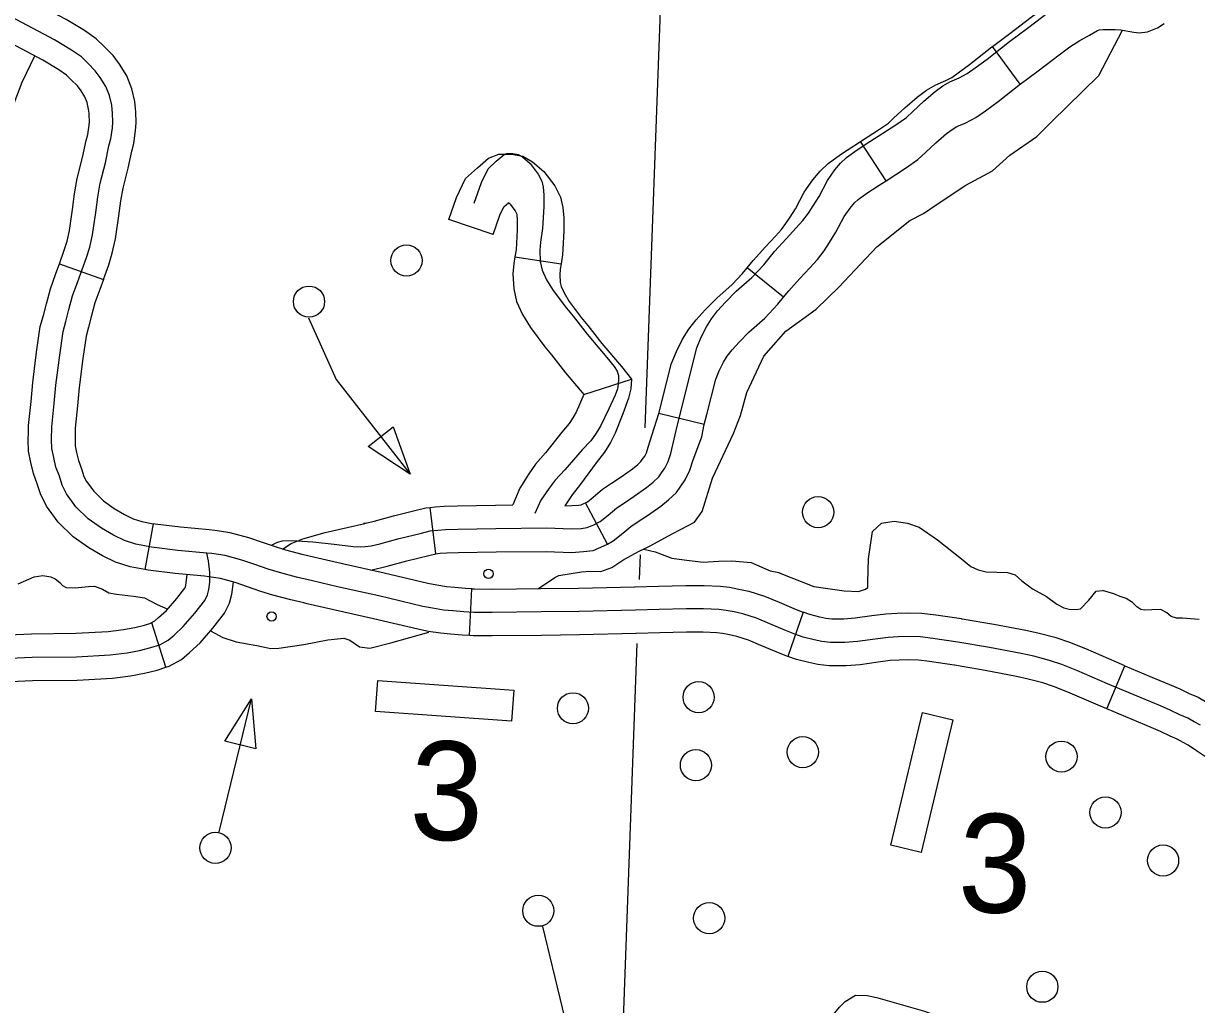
# Model space of a CAD drawing. Extents: x 653372 to 905732, y 627442 to 787275.
# Drawn here: x 719343 to 723106, y 752725 to 755873 of the extents above; entities that cross this region are included whole.
import ezdxf

# ---------------------------------------------------------------- set-up
doc = ezdxf.new("R2010")
doc.units = 0
for name, color, linetype in [('31', 7, 'Continuous'), ('32', 7, 'Continuous'), ('35', 7, 'Continuous'), ('4', 7, 'Continuous'), ('56', 7, 'Continuous')]:
    doc.layers.add(name, color=color, linetype=linetype)

msp = doc.modelspace()

# ---------------------------------------------------------------- linework, layer by layer
at = {"layer": '31'}
for p, q in [((719458.4, 755102.1), (719599.7, 755051.5)), ((719508.7, 754559), (719508.7, 754559)), ((719759.2, 754267.9), (719732.1, 754120.4)), ((720773.8, 753908.9), (720781.3, 754058.7)), ((721843.9, 753983.7), (721795.2, 753841.8)), ((721795.2, 753841.8), (721795.2, 753841.8)), ((722818, 753673.6), (722875.9, 753812))]:
    msp.add_line(p, q, dxfattribs=at)
for points in [[(719702.6, 755600.9), (719700.3, 755623.4), (719690.5, 755664.1), (719675, 755704.8), (719651.2, 755742.5), (719630.3, 755770.3), (719602.2, 755799.4), (719576.4, 755824), (719538.4, 755850.5), (719479.5, 755886.4), (719339.1, 755960.5), (719283, 755990.6)], [(719930.9, 754173.6), (719838.2, 754182.3), (719754, 754192.6), (719703.6, 754201.9), (719666.7, 754214.3), (719631.9, 754230.8), (719593.2, 754253.8), (719551.1, 754283.2), (719511.5, 754322.5), (719481, 754363.5), (719467.1, 754391.4), (719458.1, 754419.9), (719447, 754449.8), (719440.2, 754480.3), (719434, 754509.3), (719433.4, 754537.5), (719434, 754578.9), (719441.8, 754653.3), (719447.1, 754713), (719459.2, 754808.7), (719470.6, 754885.1), (719479.3, 754917.3), (719488.9, 754955), (719500.8, 754999), (719517.7, 755045), (719545.3, 755122.4), (719555.5, 755155.6), (719564.4, 755195.5), (719575, 755266.3), (719581.4, 755315.4), (719589.1, 755360.3), (719605.9, 755426.5), (719617.4, 755480.4), (719623, 755502.8), (719628.3, 755538.5), (719629.5, 755556.8), (719628.9, 755584.6), (719626.2, 755610.7), (719618.7, 755641.9), (719607.6, 755671.1), (719589.4, 755699.9), (719573.2, 755721.5), (719549.3, 755746.1), (719528.8, 755765.8), (719497.4, 755787.7), (719442.4, 755821.2), (719303.9, 755894.3)], [(719553.4, 755585.3), (719552.1, 755598), (719546.9, 755619.8), (719540.2, 755637.5), (719527.7, 755657.2), (719516.1, 755672.7), (719496.4, 755692.9), (719481.1, 755707.6), (719456.4, 755724.8), (719405.3, 755756), (719268.7, 755828.1), (719212.1, 755858.4)], [(719458.4, 755102.1), (719474.1, 755146), (719482.9, 755174.8), (719490.7, 755209.3), (719500.7, 755276.7), (719507.2, 755326.6), (719515.7, 755375.8), (719532.8, 755443.5), (719544.3, 755497.3), (719549.3, 755517.4), (719553.6, 755546.6), (719554.5, 755558.6), (719554, 755579.9), (719553.4, 755585.3)], [(719599.7, 755051.5), (719616.6, 755098.8), (719628.1, 755136.4), (719638.2, 755181.7), (719649.3, 755255.9), (719655.6, 755304.2), (719662.5, 755344.7), (719678.9, 755409.5), (719690.4, 755463.5), (719696.6, 755488.1), (719702.9, 755530.4), (719704.6, 755555), (719703.9, 755589.3), (719702.6, 755600.9)], [(719358.7, 754560.9), (719359, 754583.3), (719367.2, 754660.6), (719372.6, 754721.1), (719384.9, 754818.9), (719397.1, 754900.5), (719406.8, 754936.3), (719416.4, 754974), (719429.3, 755021.8), (719447.2, 755070.6), (719458.4, 755102.1)], [(719599.7, 755051.5), (719588.2, 755019.5), (719572.3, 754976.3), (719561.5, 754936), (719551.9, 754898.2), (719544.2, 754869.7), (719533.5, 754798.5), (719521.7, 754705), (719516.5, 754646.1), (719508.9, 754574.5), (719508.7, 754559)], [(719732.1, 754120.4), (719684.8, 754129.1), (719638.5, 754144.6), (719596.6, 754164.6), (719552.5, 754190.7), (719502.9, 754225.4), (719454.6, 754273.2), (719416.9, 754324.1), (719397.3, 754363.2), (719387.1, 754395.5), (719374.9, 754428.5), (719366.9, 754464.3), (719359.1, 754500.7), (719358.4, 754537.3), (719358.7, 754560.9)], [(719508.7, 754559), (719508.4, 754537.8), (719508.8, 754518), (719513.4, 754496.3), (719519.1, 754471.1), (719529, 754444.2), (719536.8, 754419.7), (719545.2, 754402.9), (719568.3, 754371.8), (719599.3, 754341), (719633.9, 754316.9), (719667.3, 754297), (719694.8, 754283.9), (719722.4, 754274.7), (719759.2, 754267.9)], [(720278, 754159.3), (720237.1, 754169.2), (720184.5, 754183), (720151.6, 754193.1), (720109.8, 754207.6), (720065.6, 754222.5), (720005.8, 754238.9), (719957.3, 754246.2), (719938.6, 754248.2), (719846.3, 754256.9), (719765.4, 754266.8), (719759.2, 754267.9)], [(721382.2, 753992.4), (721306.7, 753990.2), (721125.5, 753986), (721003.8, 753984.5), (720846.4, 753982.9), (720787.5, 753983.3), (720755.6, 753984.9), (720720, 753987.9), (720690.6, 753990.7), (720655.6, 753996.3), (720624.4, 754002.3), (720483.1, 754036), (720350.3, 754065.6), (720270.2, 754084), (720218.8, 754096.4), (720163.9, 754110.9), (720128.3, 754121.8), (720085.5, 754136.7), (720043.7, 754150.7), (719990.3, 754165.4), (719947.6, 754171.8), (719930.9, 754173.6)], [(720781.3, 754058.7), (720760.6, 754059.8), (720726.7, 754062.6), (720700.1, 754065.2), (720668.6, 754070.1), (720640.3, 754075.6), (720500, 754109.1), (720366.9, 754138.7), (720287.4, 754157), (720278, 754159.3)], [(720242.8, 754013.5), (720200.4, 754023.7), (720143.4, 754038.7), (720105, 754050.5), (720061.2, 754065.7), (720021.8, 754079), (719974.7, 754091.9), (719937.9, 754097.4), (719923.3, 754099), (719830.2, 754107.8), (719742.7, 754118.5), (719732.1, 754120.4)], [(720781.3, 754058.7), (720789.7, 754058.3), (720846.3, 754057.9), (721003, 754059.5), (721124.1, 754061), (721303.7, 754065.1)], [(721303.8, 754065.1), (721304.7, 754065.1), (721380.3, 754067.3), (721467.7, 754069.2), (721526.5, 754069.5), (721579.4, 754067.2), (721608.5, 754063.9), (721638.1, 754057.9), (721670.3, 754051.1), (721720.6, 754034.8), (721766.8, 754015.6), (721813.9, 753995.3), (721843.5, 753983.8), (721843.9, 753983.7)], [(720773.8, 753908.9), (720750.6, 753910.1), (720713.3, 753913.2), (720681.2, 753916.3), (720642.6, 753922.4), (720608.6, 753929), (720466.3, 753962.9), (720333.8, 753992.4), (720253, 754011), (720242.8, 754013.5)], [(723118.6, 753621.5), (723099.1, 753631.7), (723078, 753643.8), (723052.3, 753654.8), (723021.8, 753669.2), (722990.2, 753682.9), (722928.9, 753708.5), (722820.2, 753754), (722722, 753796.6), (722673.9, 753816), (722634.6, 753829.3), (722583.8, 753842.4), (722543.8, 753851.2), (722442.1, 753870.7), (722340.8, 753888.1), (722259.9, 753899.4), (722219.7, 753904.5), (722178.8, 753905.7), (722149.3, 753904.7), (722116.7, 753903.1), (722074.9, 753897.3), (722019, 753890), (721978.3, 753886.8), (721953.3, 753886.2), (721932.2, 753886.2), (721904.1, 753889.6), (721880, 753894.9), (721844.4, 753904.2), (721817.8, 753913.4), (721785.6, 753925.8), (721737.6, 753946.5), (721694.6, 753964.4), (721650.9, 753978.5), (721622.9, 753984.5), (721596.8, 753989.8), (721573.6, 753992.4), (721525, 753994.5), (721468.7, 753994.2), (721382.2, 753992.4)], [(722354.6, 753961.8), (722352.3, 753962.2), (722269.8, 753973.8), (722225.5, 753979.4), (722178.6, 753980.8), (722146.2, 753979.6), (722109.7, 753977.9), (722064.9, 753971.7), (722011.2, 753964.6), (721974.5, 753961.7), (721952.5, 753961.2), (721936.7, 753961.2), (721916.6, 753963.7), (721897.5, 753967.8), (721866.2, 753976.1), (721843.9, 753983.7)], [(722875.9, 753812), (722849.6, 753823), (722750.9, 753865.8), (722700, 753886.3), (722656.1, 753901.2), (722601.3, 753915.3), (722559, 753924.7), (722455.5, 753944.5), (722354.6, 753961.8)], [(721307.2, 753915.1), (721126.8, 753911), (721004.7, 753909.5), (720846.5, 753907.8), (720785.4, 753908.4), (720773.8, 753908.9)], [(721795.2, 753841.8), (721792.1, 753842.9), (721757.2, 753856.4), (721708.3, 753877.4), (721668.6, 753894), (721631.5, 753906), (721607.7, 753911.1), (721585.2, 753915.6), (721567.7, 753917.6), (721523.5, 753919.5), (721469.6, 753919.3), (721384.1, 753917.4), (721308.6, 753915.2), (721307.1, 753915.1)], [(722329.3, 753813.9), (722329.2, 753813.9), (722250, 753825.1), (722213.9, 753829.6), (722179, 753830.7), (722152.5, 753829.7), (722123.6, 753828.4), (722084.9, 753823), (722026.8, 753815.4), (721982.1, 753811.8), (721954.1, 753811.2), (721927.7, 753811.2), (721891.7, 753815.6), (721862.5, 753821.9), (721822.7, 753832.4), (721795.2, 753841.8)], [(722818, 753673.6), (722790.8, 753685), (722693, 753727.4), (722647.8, 753745.6), (722613.2, 753757.4), (722566.4, 753769.4), (722528.6, 753777.8), (722428.7, 753796.9), (722329.3, 753813.9)], [(722875.9, 753812), (722957.8, 753777.7), (723019.6, 753751.9), (723052.7, 753737.5), (723083.1, 753723.3), (723111.7, 753711), (723135.2, 753697.4), (723157.7, 753685.7), (723190.4, 753662.7), (723227.7, 753637.9), (723271.5, 753605.1), (723294.3, 753590.6), (723346.9, 753562.3)], [(723275.9, 753430.2), (723218.6, 753461), (723186.2, 753481.5), (723141.2, 753515.3), (723105.7, 753538.8), (723079.5, 753557.3), (723063, 753565.9), (723044.3, 753576.7), (723021.6, 753586.4), (722990.9, 753600.8), (722960.8, 753613.9), (722900, 753639.2), (722818, 753673.6)]]:
    msp.add_lwpolyline(points, dxfattribs=at)
at = {"layer": '32'}
for p, q in [((722540.4, 755678.8), (722451.3, 755799.4)), ((722110.3, 755368.7), (722028.4, 755494.5)), ((720849.5, 755196), (720707.6, 755244.5)), ((720919.6, 755124.8), (721067.7, 755101.5)), ((721781.3, 754994.6), (721664.9, 755089.2)), ((721140.9, 754682.8), (721294.1, 754731.6)), ((721527, 754586.2), (721381.3, 754621.8)), ((720665.4, 754171.1), (720648.2, 754320.1)), ((721216.9, 754202.7), (721145.9, 754334.9)), ((719800, 753807), (719754.5, 753949.9))]:
    msp.add_line(p, q, dxfattribs=at)
for points in [[(722451.3, 755799.4), (722507.6, 755841), (722575.4, 755893.1), (722615.7, 755922.3), (722654.8, 755947.3), (722687.3, 755965.2), (722725.8, 755988.8), (722762.7, 756000.2), (722798.8, 756004.5), (722850.1, 756003.7), (722881.1, 756002), (722911.5, 755996.3), (722915.1, 755995.8), (722919.7, 755998.9)], [(721843.5, 755241.2), (721861.1, 755264.3), (721876.9, 755288), (721895.4, 755317.7), (721922.9, 755369.5), (721946.3, 755403.3), (721964.5, 755425.2), (721983.2, 755443.4), (722017.2, 755467.8), (722058.6, 755494.4), (722141.3, 755548.2), (722175.9, 755571.9), (722196.4, 755591.3), (722231.3, 755623.5), (722267.9, 755655.1), (722292, 755673.2), (722314.8, 755686.4), (722344.9, 755699.4), (722370.7, 755712.6), (722396.6, 755730.5), (722435, 755759), (722506.3, 755815.6), (722563.6, 755858), (722631.1, 755909.8)], [(722540.4, 755678.8), (722597.9, 755721.2), (722665.1, 755772.8), (722700.2, 755798.3), (722731.5, 755818.3), (722762.6, 755835.5), (722788.1, 755851.1), (722794, 755852.9), (722806.5, 755854.4), (722844.7, 755853.8), (722863.2, 755852.8), (722886.9, 755848.3), (722905.2, 755845.7), (722922.1, 755843.7), (722949.2, 755846.8), (722980.9, 755859.6), (723002, 755873.5)], [(722028.4, 755494.5), (722088.7, 755533.7), (722117.8, 755553.6), (722134.4, 755569.3), (722170.4, 755602.6), (722210, 755636.8), (722239.7, 755659), (722270.1, 755676.6), (722302, 755690.4), (722321.2, 755700.2), (722342, 755714.6), (722378.4, 755741.7), (722449.7, 755798.3), (722451.2, 755799.4)], [(722110.3, 755368.7), (722172.1, 755409), (722212.2, 755436.5), (722236.7, 755459.6), (722270.3, 755490.7), (722304, 755519.8), (722322.6, 755533.6), (722337.8, 755542.5), (722365.9, 755554.7), (722398.3, 755571.2), (722429.5, 755592.7), (722469.8, 755622.7), (722541, 755679.2), (722540.5, 755678.8)], [(721664.9, 755089.2), (721684.4, 755113.1), (721723.4, 755156), (721755.3, 755190.7), (721774.9, 755212.4), (721789.2, 755231), (721803, 755251.7), (721819.4, 755278.3), (721847.9, 755331.8), (721875.7, 755371.9), (721898.5, 755399.3), (721924.1, 755424.2), (721964.2, 755453), (722007, 755480.5), (722028.4, 755494.5)], [(720707.6, 755244.5), (720731.7, 755315.2), (720761.3, 755375.8), (720799.1, 755410.4), (720834.7, 755441), (720868.3, 755453.8), (720908.4, 755454.1), (720945.5, 755447), (720975.9, 755429.8), (721012.5, 755398.5), (721047.4, 755352.5), (721066, 755316.1), (721073.8, 755283.2), (721076.6, 755249.8), (721077, 755207.3), (721072.3, 755130.7), (721067.7, 755101.5)], [(720789.4, 755297.1), (720812.1, 755363.4), (720833.3, 755407), (720859.7, 755431.1), (720884.6, 755452.5), (720893.2, 755455.8), (720912.5, 755455.9), (720930.2, 755452.5), (720943.5, 755445), (720968.5, 755423.6), (720994.6, 755389.3), (721006, 755366.8), (721010.4, 755348.2), (721012.5, 755323.2), (721012.8, 755286.1), (721008.6, 755215.7), (721001.5, 755171), (720999.3, 755145.4), (721001.1, 755109), (721007.4, 755081.7), (721021.4, 755050.6), (721042.3, 755016.2), (721084.8, 754959.3), (721106.3, 754933.9)], [(721781.3, 754994.6), (721798.1, 755015.3), (721834.1, 755054.8), (721866.1, 755089.6), (721890.3, 755116.3), (721911.3, 755143.8), (721929.1, 755170.5), (721949.5, 755203.4), (721976.2, 755253.6), (721995.2, 755281), (722008.8, 755297.3), (722020.6, 755308.9), (722048.5, 755328.9), (722088.4, 755354.5), (722110.3, 755368.7)], [(720849.5, 755196), (720870.7, 755257.9), (720883.6, 755284.4), (720898.6, 755298.1), (720898.8, 755298.3), (720902.8, 755295), (720919.9, 755272.4), (720924.2, 755263.9), (720925.3, 755259.5), (720926.7, 755242.9), (720926.9, 755211.2), (720923.1, 755146.9), (720919.6, 755124.8)], [(720139.2, 754198.6), (720158.2, 754209), (720173.5, 754212.7), (720202.6, 754214.3), (720270.8, 754209.8), (720340.1, 754201.7), (720401, 754194.4), (720422.8, 754193.7), (720439.7, 754194.5), (720458.6, 754196.9), (720486, 754203.4), (720548.4, 754220.2), (720620.4, 754238), (720647.2, 754244.5), (720672.1, 754247.4), (720696.9, 754249.7), (720736.9, 754250.3), (720858, 754252.7), (721021.5, 754254.1), (721100.2, 754250.9), (721132.3, 754252.9), (721151.1, 754255.4), (721173.2, 754264.4), (721193.5, 754275.3), (721218.3, 754295.1), (721246.2, 754319.1), (721270.9, 754335.3), (721302.4, 754356.2), (721341.9, 754384), (721363, 754401.5), (721381.1, 754418), (721389.9, 754431), (721400.9, 754446.6), (721411.2, 754467.5), (721419.3, 754493.3), (721437.2, 754567.2), (721473.1, 754713.8), (721503.3, 754832.4), (721517.6, 754866.5), (721533.7, 754899.9), (721550.2, 754925.4), (721569.7, 754950.9), (721595.4, 754979.1), (721629.7, 755013.8), (721680.1, 755058.5), (721717.6, 755098.5), (721752.1, 755141), (721789.7, 755182.3), (721821.6, 755217), (721843.5, 755241.2)], [(720919.6, 755124.8), (720916.2, 755103.2), (720913.3, 755069.9), (720915.6, 755021.8), (720925.1, 754980.7), (720944.1, 754938.8), (720969.1, 754897.4), (721015.1, 754835.8), (721037, 754809.9), (721081.8, 754751.6), (721140.9, 754682.8)], [(721067.7, 755101.5), (721065.2, 755085.1), (721063.6, 755067.1), (721064.8, 755042.4), (721067.9, 755028.9), (721077.1, 755008.8), (721093.7, 754981.3), (721132.6, 754929.2), (721153.8, 754904.1), (721198.3, 754846.3), (721261.9, 754772.1), (721294.1, 754731.6)], [(721381.3, 754621.8), (721389.4, 754655.1), (721421.1, 754779.5), (721438.3, 754820.5), (721457.3, 754859.8), (721478, 754891.8), (721501.2, 754922.1), (721530.1, 754953.9), (721567.2, 754991.5), (721616.8, 755035.4), (721650.1, 755071), (721664.9, 755089.2)], [(721527, 754586.2), (721535, 754618.8), (721563.7, 754731.6), (721575.1, 754758.8), (721588.4, 754786.2), (721600.7, 754805.3), (721616.5, 754825.9), (721639, 754850.7), (721670.4, 754882.5), (721721.5, 754927.8), (721763.2, 754972.3), (721781.3, 754994.6)], [(721106.3, 754933.9), (721150.9, 754875.8), (721215, 754801.2), (721237.6, 754772.7), (721247.1, 754757.4), (721251.7, 754743.8), (721252.1, 754731.6), (721250.9, 754715.3), (721248.3, 754701.1), (721241.3, 754680.6), (721221.4, 754636.6), (721194.1, 754581.1), (721179.9, 754558), (721162.8, 754534.3), (721135.5, 754504.5), (721080.2, 754440.5), (721048.6, 754407.1), (721029.3, 754382), (721003.1, 754343.5), (720993.2, 754322.4), (720983.3, 754300.6)], [(721294.1, 754731.6), (721291.1, 754700.6), (721283.5, 754670.8), (721265.7, 754620.8), (721241.2, 754558.8), (721226.1, 754529), (721207.4, 754497.9), (721180.6, 754463.3), (721130.3, 754394.6), (721103, 754360.4), (721079.9, 754324.7)], [(721140.9, 754682.8), (721115.9, 754626.3), (721105.8, 754608.1), (721093.6, 754589.6), (721069.7, 754561.2), (721017.5, 754495.4), (720986, 754459), (720964.4, 754428.3), (720935.5, 754381.8), (720913.1, 754328.2)], [(721145.9, 754334.9), (721152, 754338.2), (721170.4, 754352.9), (721201, 754379.2), (721229.6, 754397.9), (721260.1, 754418.1), (721296.3, 754443.6), (721313.8, 754458.2), (721324, 754467.4), (721328.2, 754473.6), (721336.2, 754485), (721341.4, 754495.4), (721347, 754513.3), (721366.5, 754574.4), (721381.3, 754621.8)], [(721216.9, 754202.7), (721235, 754212.5), (721266.1, 754237.4), (721291.4, 754259.1), (721312.2, 754272.7), (721344.7, 754294.2), (721387.6, 754324.4), (721412.2, 754344.9), (721438.1, 754368.5), (721451.6, 754388.4), (721465.6, 754408.3), (721481.1, 754439.6), (721491.6, 754473.3), (721518.9, 754546.3), (721527, 754586.2)], [(720434.1, 754269.4), (720445.1, 754270.8), (720467.6, 754276.1), (720529.6, 754292.8), (720602.6, 754310.9), (720634, 754318.5), (720648.2, 754320.1)], [(720648.2, 754320.1), (720664.3, 754322), (720692.9, 754324.6), (720735.6, 754325.3), (720856.9, 754327.7), (720913.1, 754328.2)], [(721079.9, 754324.7), (721125, 754327.6), (721131.7, 754328.5), (721141.2, 754332.4), (721145.9, 754334.9)], [(720173.6, 754185.9), (720201.4, 754204.2), (720239, 754219.7), (720311, 754239.9), (720381, 754255.8), (720437.7, 754268.4), (720445.1, 754270.8)], [(720665.4, 754171.1), (720679.8, 754172.8), (720701, 754174.7), (720738.2, 754175.3), (720859.1, 754177.7), (721020.3, 754179.1), (721101, 754175.8), (721139.6, 754178.2), (721170.5, 754182.3), (721205.2, 754196.5), (721216.9, 754202.7)], [(719298.5, 753836.6), (719370.5, 753839.1), (719513.2, 753841), (719621.6, 753847), (719675.2, 753853.9), (719715.6, 753861.2), (719751.5, 753870.2), (719780.4, 753879.4), (719807.1, 753894.1), (719826.1, 753910.5), (719855.6, 753937.5), (719892.4, 753980.3), (719924.6, 754021.1), (719933.6, 754039.4), (719938, 754056.3), (719941, 754080.2), (719941.2, 754111.5), (719936.9, 754148.8), (719930.9, 754173.6)], [(720457.9, 754119.1), (720509.5, 754131.2), (720572.4, 754148.2), (720643.3, 754165.8), (720665.4, 754171.1), (720670.6, 754171.7)], [(719750.7, 753948.7), (719764.1, 753956), (719776.3, 753966.6), (719801.6, 753989.8), (719834.5, 754028), (719860.8, 754061.4), (719863, 754065.7), (719864.2, 754070.5), (719868.5, 754104.2)], [(719800, 753807), (719810, 753810.1), (719850.1, 753832.1), (719876, 753854.5), (719909.5, 753885.2), (719950.3, 753932.6), (719988.3, 753980.8), (720004.3, 754013.1), (720011.8, 754042.1), (720016.7, 754080.7)], [(719240.1, 753905.9), (719257.6, 753909), (719294.7, 753911.5), (719368.7, 753914.1), (719510.6, 753916), (719614.7, 753921.8), (719663.7, 753928.1), (719699.8, 753934.6), (719731, 753942.4), (719754.5, 753949.9)], [(719266.4, 753758.2), (719275.9, 753759.9), (719302.4, 753761.7), (719372.3, 753764.1), (719515.8, 753766), (719628.5, 753772.3), (719686.7, 753779.8), (719731.4, 753787.9), (719772, 753798), (719800, 753807)], [(721844.3, 752576.1), (721961.2, 752716.4), (721978.8, 752734.2), (722011.8, 752754.8), (722050.8, 752753.7), (722083.8, 752746), (722233.2, 752702.8), (722318, 752672), (722355.5, 752658), (722380.2, 752644.1)]]:
    msp.add_lwpolyline(points, dxfattribs=at)
at = {"layer": '35'}
for points in [[(721642.9, 754614.9), (721663.6, 754688.8), (721718.5, 754805.1), (721788.7, 754886), (721885.9, 754956.4), (721958.6, 755027.5), (722080.6, 755156.8), (722186.2, 755240.5), (722230.4, 755263.6), (722280.2, 755297.4), (722366.1, 755354.6), (722451.7, 755400.9), (722507.5, 755450.8), (722593.4, 755510.7), (722641, 755558.1), (722793.1, 755706.1), (722869.2, 755852.4)], [(718820.4, 754381.6), (718867.8, 754501.1), (718914.3, 754586.1), (718938.9, 754629.3), (718969, 754672.2), (719020.7, 754751.6), (719067.4, 754798.2), (719120.6, 754835.1), (719143.7, 754872.8), (719154.1, 754899.9), (719151, 754932.9), (719149.1, 755007), (719167.8, 755081.9), (719181.2, 755118.6), (719244.2, 755250.4), (719256.8, 755304.9), (719258.1, 755350.1), (719259.2, 755385.7), (719274.1, 755425.1), (719282.6, 755479.4), (719287.2, 755542.4), (719304.6, 755594.6), (719338.5, 755685.3), (719379.1, 755769.8)], [(721425.9, 754236.2), (721451.2, 754249.4), (721495.4, 754272.6), (721520.5, 754307.4), (721553.7, 754413.7), (721621.3, 754557.5), (721642.9, 754614.9)], [(721766.2, 754111.7), (721778.4, 754105.8), (721878.2, 754066.5), (721976, 754052.8), (722021.6, 754050.1), (722044.7, 754057.5), (722051.6, 754062.6), (722052.2, 754080.1), (722054.4, 754155.4), (722066.4, 754242.6), (722095.5, 754270), (722136.6, 754276.3), (722179, 754270.1), (722216.2, 754256.9), (722275.6, 754216.1), (722351.8, 754154.6), (722382, 754130.8), (722405.9, 754119.3), (722431.2, 754113.2), (722499.3, 754111.1), (722524.6, 754103.6), (722545.5, 754084.2), (722579.8, 754058.9), (722624.8, 754034.7), (722657.7, 754009.5), (722680.2, 753998), (722697.6, 753993.5), (722720.4, 753992.8), (722733.9, 753995.1), (722760.3, 754022.5), (722784.1, 754051.4), (722805, 754053.4)], [(720995.7, 754059.4), (721047.4, 754095.3), (721060.9, 754101.1), (721133, 754113.3), (721161.8, 754115), (721195.2, 754114.5), (721230.6, 754126.9), (721269.5, 754153.1), (721318.3, 754179.7), (721338.5, 754189), (721353, 754196.8), (721425.9, 754236.2)], [(721333.5, 754186.2), (721370, 754177.5), (721423.4, 754157.3), (721462.2, 754151.6), (721523.5, 754144.4), (721572.5, 754148.1), (721615.2, 754148.9), (721677.5, 754143.4), (721738, 754116.6), (721766.2, 754111.7)], [(719326.2, 754075), (719376.9, 754097.3), (719405.4, 754101.1), (719431.3, 754097.4), (719445, 754090.9), (719459.8, 754079.4), (719468.3, 754069), (719479.9, 754063.3), (719509.4, 754061.5), (719552, 754066.6), (719570.4, 754066.9), (719596.7, 754058.2), (719616.7, 754046.4), (719641.7, 754041.3), (719696.4, 754035.8), (719731.3, 754029.4), (719771.6, 754008.5), (719806.1, 753993.9)], [(723114.5, 753960.2), (723086.4, 753962.9), (723061.5, 753964.3), (723042.3, 753964.3), (723024.5, 753969.9), (723010.8, 753981.9), (722991.5, 753992.7), (722962.7, 753991), (722939.6, 753990.4), (722927.5, 753992), (722914.3, 754001.4), (722900.7, 754015.2), (722880, 754028), (722860.9, 754033.7), (722840.6, 754043.3), (722805, 754053.4)], [(719943.3, 753924.4), (719982.7, 753902.4), (720025.6, 753888.5), (720091.8, 753876.6), (720136.4, 753867.5), (720162.6, 753868.7), (720242.7, 753879.9), (720319.8, 753895.6), (720370.9, 753900.2), (720390.2, 753894), (720421.4, 753872.8), (720454.3, 753868.6), (720521.8, 753885.3), (720643.3, 753919.8)]]:
    msp.add_lwpolyline(points, dxfattribs=at)
at = {"layer": '4'}
for points in [[(721416.3, 756762.5), (721416.2, 756759.7), (721336.1, 754575.1)], [(721321.2, 754167.9), (721318.3, 754088.6)], [(721310.8, 753883.4), (721247.2, 752147.5)]]:
    msp.add_lwpolyline(points, dxfattribs=at)
at = {"layer": '56'}
for p, q in [((720448.8, 754516), (720529.2, 754578.7)), ((720529.2, 754578.7), (720583.1, 754426.7)), ((720583.1, 754426.7), (720448.8, 754516)), ((719989.1, 753569.7), (720074.9, 753706.2)), ((720074.9, 753706.2), (720088.1, 753545.5)), ((720088.1, 753545.5), (719989.1, 753569.7))]:
    msp.add_line(p, q, dxfattribs=at)
for points in [[(720257.5, 754928.7), (720345.8, 754730.9), (720583.1, 754426.7)], [(719970.4, 753278.4), (720074.9, 753706.2)], [(721008.2, 752975.4), (721134.2, 752452.9)]]:
    msp.add_lwpolyline(points, dxfattribs=at)
for points in [[(720472.7, 753665.3), (720479.9, 753765), (720916.2, 753733.6), (720909, 753633.9)], [(722226.7, 753661.7), (722324, 753638.6), (722222.9, 753212.9), (722125.6, 753236)]]:
    msp.add_lwpolyline(points, close=True, dxfattribs=at)
for centre, radius in [((720571.8, 755112.5), 50), ((720259, 754980.7), 50), ((721892.3, 754304.8), 50), ((720834.9, 754107.4), 15), ((720139.2, 753970.1), 15), ((721508.9, 753710.9), 50), ((721105.8, 753675.5), 50), ((721843.1, 753534.8), 50), ((722672.9, 753520.3), 50), ((721500.3, 753492.8), 50), ((722814, 753341.1), 50), ((719958.8, 753227.6), 50), ((722998.9, 753186.9), 50), ((720994.6, 753025.6), 50), ((721542.9, 753001.7), 50), ((722611.6, 752781.7), 50)]:
    msp.add_circle(centre, radius, dxfattribs=at)

# ---------------------------------------------------------------- texts
for p in [(720579.1, 753256), (722338.1, 753023.1)]:
    msp.add_text('3', height=316.8, rotation=358.28, dxfattribs=at).set_placement(p)

doc.saveas('drawing.dxf')
